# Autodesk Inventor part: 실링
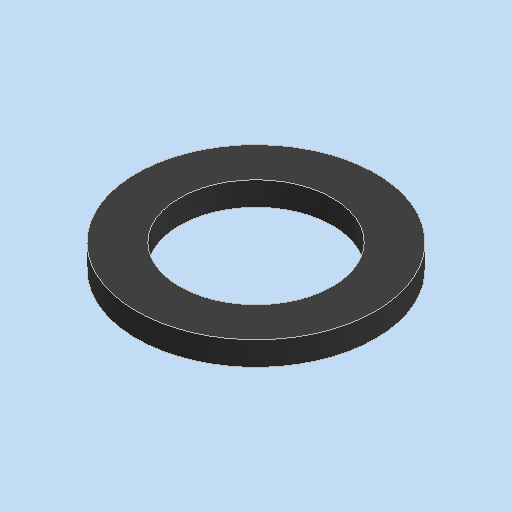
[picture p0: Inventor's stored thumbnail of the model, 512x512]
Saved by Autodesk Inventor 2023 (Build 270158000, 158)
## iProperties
Created: 2024-11
Part Number: 실링
Material: 고무
Document SubType Name: Modeling
Designer: asung
Density: 0.93 g/cm^3
Appearance: 기본값
Author: jhkim
Sending System: Autodesk Inventor 2025
Preprocessor: ST-DEVELOPER v20
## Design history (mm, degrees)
feature "솔리드1"
node "솔리드2"
